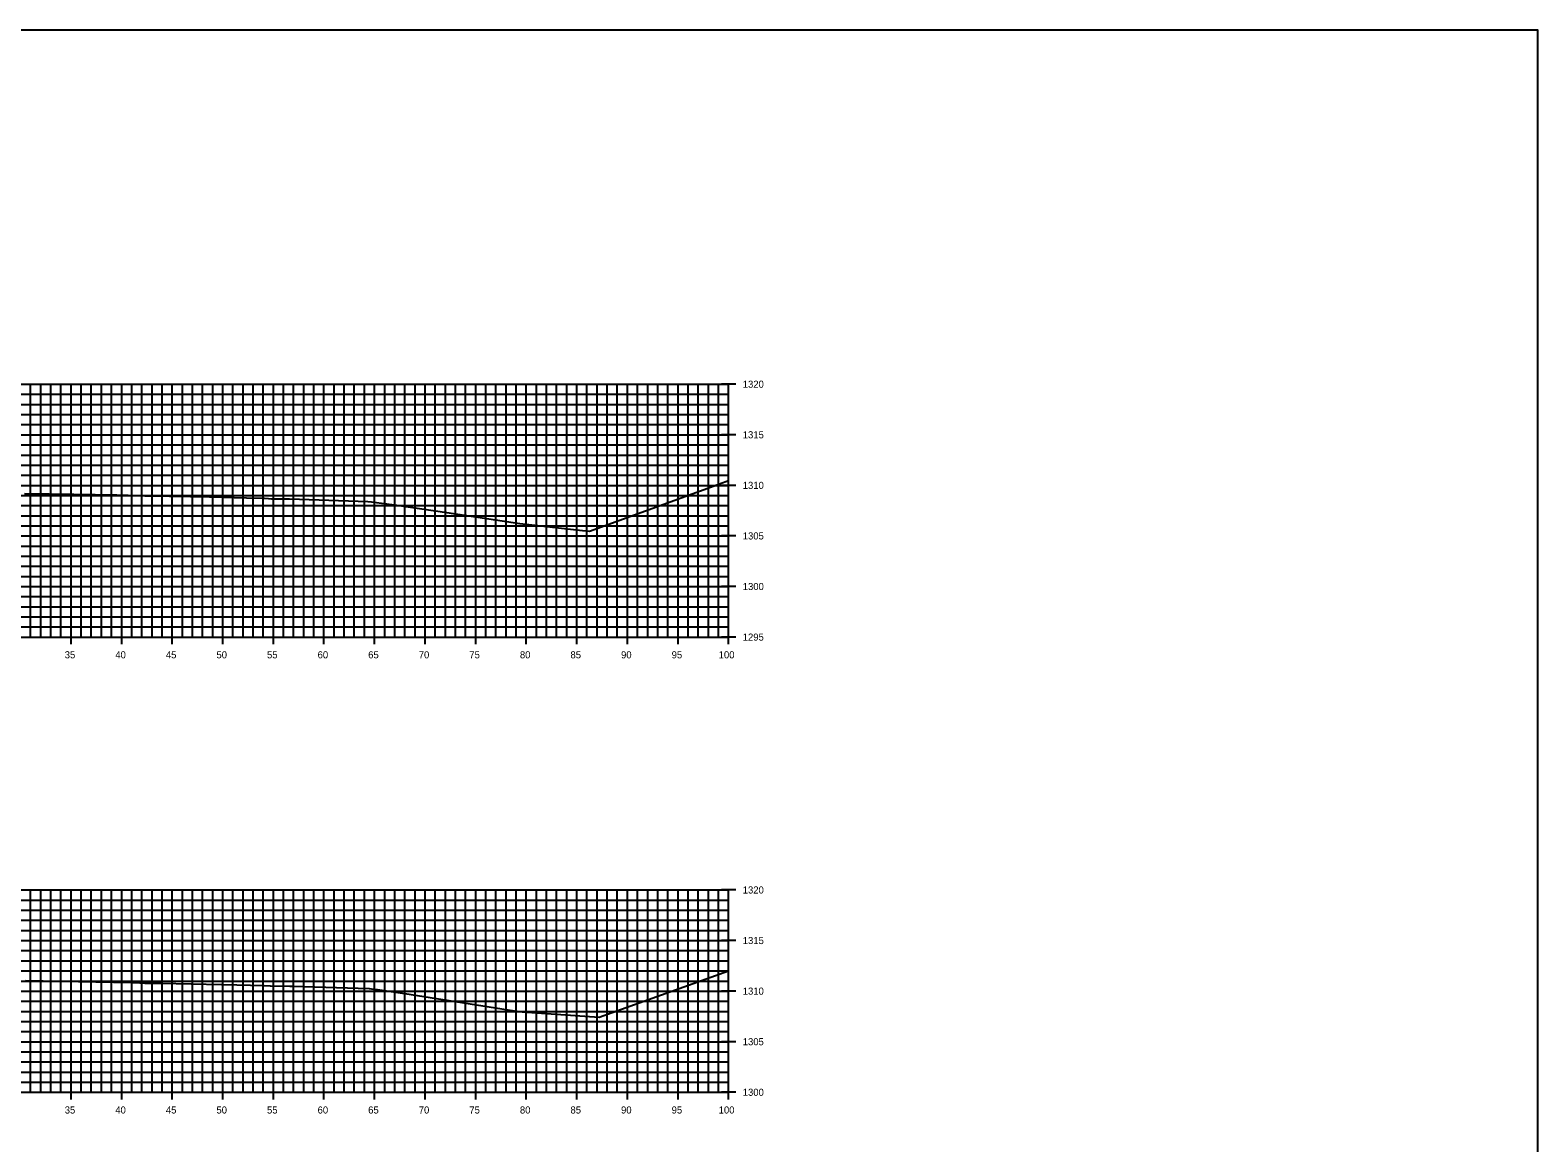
# Model space of a CAD drawing. Extents: x 674939 to 678919, y 750652 to 765176.
# Drawn here: x 678769.5 to 678918.5, y 753792.6 to 753902.6 of the extents above; entities that cross this region are included whole.
import ezdxf

# ---------------------------------------------------------------- set-up
doc = ezdxf.new("R2010")
doc.units = 0
for name, color, linetype in [('R_Axis', 7, 'Continuous'), ('R_Axis Annot', 7, 'Continuous'), ('R_Exist Surface', 7, 'Continuous'), ('R_Grid', 7, 'Continuous'), ('R_No Plot', 7, 'Continuous')]:
    doc.layers.add(name, color=color, linetype=linetype)

msp = doc.modelspace()

# ---------------------------------------------------------------- linework, layer by layer
at = {"layer": 'R_Axis'}
for p, q in [((678839.23, 753867.55), (678837.83, 753867.55)), ((678838.53, 753842.55), (678838.53, 753867.55)), ((678839.23, 753862.55), (678837.83, 753862.55)), ((678839.23, 753857.55), (678837.83, 753857.55)), ((678839.23, 753852.55), (678837.83, 753852.55)), ((678839.23, 753847.55), (678837.83, 753847.55)), ((678773.53, 753841.85), (678773.53, 753843.25)), ((678778.53, 753841.85), (678778.53, 753843.25)), ((678783.53, 753841.85), (678783.53, 753843.25)), ((678788.53, 753841.85), (678788.53, 753843.25)), ((678793.53, 753841.85), (678793.53, 753843.25)), ((678798.53, 753841.85), (678798.53, 753843.25)), ((678803.53, 753841.85), (678803.53, 753843.25)), ((678808.53, 753841.85), (678808.53, 753843.25)), ((678813.53, 753841.85), (678813.53, 753843.25)), ((678818.53, 753841.85), (678818.53, 753843.25)), ((678823.53, 753841.85), (678823.53, 753843.25)), ((678828.53, 753841.85), (678828.53, 753843.25)), ((678833.53, 753841.85), (678833.53, 753843.25)), ((678838.53, 753841.85), (678838.53, 753843.25)), ((678638.53, 753842.55), (678838.53, 753842.55)), ((678839.23, 753842.55), (678837.83, 753842.55)), ((678839.23, 753817.55), (678837.83, 753817.55)), ((678838.53, 753797.55), (678838.53, 753817.55)), ((678839.23, 753812.55), (678837.83, 753812.55)), ((678839.23, 753807.55), (678837.83, 753807.55)), ((678839.23, 753802.55), (678837.83, 753802.55)), ((678773.53, 753796.85), (678773.53, 753798.25)), ((678778.53, 753796.85), (678778.53, 753798.25)), ((678783.53, 753796.85), (678783.53, 753798.25)), ((678788.53, 753796.85), (678788.53, 753798.25)), ((678793.53, 753796.85), (678793.53, 753798.25)), ((678798.53, 753796.85), (678798.53, 753798.25)), ((678803.53, 753796.85), (678803.53, 753798.25)), ((678808.53, 753796.85), (678808.53, 753798.25)), ((678813.53, 753796.85), (678813.53, 753798.25)), ((678818.53, 753796.85), (678818.53, 753798.25)), ((678823.53, 753796.85), (678823.53, 753798.25)), ((678828.53, 753796.85), (678828.53, 753798.25)), ((678833.53, 753796.85), (678833.53, 753798.25)), ((678838.53, 753796.85), (678838.53, 753798.25)), ((678638.53, 753797.55), (678838.53, 753797.55)), ((678839.23, 753797.55), (678837.83, 753797.55))]:
    msp.add_line(p, q, dxfattribs=at)
at = {"layer": 'R_Exist Surface'}
for points in [[(678768.92, 753856.76), (678773.81, 753856.68), (678778.05, 753856.61), (678780.33, 753856.55), (678780.83, 753856.53), (678780.98, 753856.51), (678781.5, 753856.51), (678782.51, 753856.5), (678783.27, 753856.49), (678785.32, 753856.45), (678787.22, 753856.42), (678790.86, 753856.33), (678792.6, 753856.28), (678792.64, 753856.28), (678792.66, 753856.28), (678793.04, 753856.25), (678793.33, 753856.23), (678793.84, 753856.23), (678795.11, 753856.22), (678798.04, 753856.12), (678802.86, 753855.94), (678803.24, 753855.91), (678803.46, 753855.88), (678805.51, 753855.61), (678806.86, 753855.43), (678810.69, 753854.86), (678817.89, 753853.77), (678824.09, 753853.08), (678824.79, 753853.01), (678826.33, 753853.58), (678836.74, 753857.38), (678838.53, 753858.03)], [(678769.03, 753808.6), (678779.46, 753808.41), (678779.84, 753808.41), (678780.81, 753808.34), (678780.84, 753808.34), (678782.19, 753808.35), (678782.4, 753808.34), (678788.39, 753808.22), (678788.57, 753808.22), (678792.61, 753808.11), (678792.61, 753808.11), (678792.63, 753808.11), (678793.21, 753808.06), (678793.23, 753808.06), (678795.16, 753808.05), (678795.23, 753808.05), (678795.48, 753808.05), (678803.01, 753807.82), (678803.03, 753807.82), (678803.42, 753807.75), (678803.43, 753807.75), (678803.58, 753807.73), (678806.52, 753807.31), (678817.38, 753805.59), (678817.58, 753805.56), (678817.67, 753805.55), (678825.72, 753804.96), (678825.72, 753804.96), (678838.53, 753809.57)]]:
    msp.add_lwpolyline(points, dxfattribs=at)
at = {"layer": 'R_Grid'}
for p, q in [((678638.53, 753867.55), (678838.53, 753867.55)), ((678769.53, 753842.55), (678769.53, 753867.55)), ((678770.53, 753842.55), (678770.53, 753867.55)), ((678771.53, 753842.55), (678771.53, 753867.55)), ((678772.53, 753842.55), (678772.53, 753867.55)), ((678773.53, 753842.55), (678773.53, 753867.55)), ((678774.53, 753842.55), (678774.53, 753867.55)), ((678775.53, 753842.55), (678775.53, 753867.55)), ((678776.53, 753842.55), (678776.53, 753867.55)), ((678777.53, 753842.55), (678777.53, 753867.55)), ((678778.53, 753842.55), (678778.53, 753867.55)), ((678779.53, 753842.55), (678779.53, 753867.55)), ((678780.53, 753842.55), (678780.53, 753867.55)), ((678781.53, 753842.55), (678781.53, 753867.55)), ((678782.53, 753842.55), (678782.53, 753867.55)), ((678783.53, 753842.55), (678783.53, 753867.55)), ((678784.53, 753842.55), (678784.53, 753867.55)), ((678785.53, 753842.55), (678785.53, 753867.55)), ((678786.53, 753842.55), (678786.53, 753867.55)), ((678787.53, 753842.55), (678787.53, 753867.55)), ((678788.53, 753842.55), (678788.53, 753867.55)), ((678789.53, 753842.55), (678789.53, 753867.55)), ((678790.53, 753842.55), (678790.53, 753867.55)), ((678791.53, 753842.55), (678791.53, 753867.55)), ((678792.53, 753842.55), (678792.53, 753867.55)), ((678793.53, 753842.55), (678793.53, 753867.55)), ((678794.53, 753842.55), (678794.53, 753867.55)), ((678795.53, 753842.55), (678795.53, 753867.55)), ((678796.53, 753842.55), (678796.53, 753867.55)), ((678797.53, 753842.55), (678797.53, 753867.55)), ((678798.53, 753842.55), (678798.53, 753867.55)), ((678799.53, 753842.55), (678799.53, 753867.55)), ((678800.53, 753842.55), (678800.53, 753867.55)), ((678801.53, 753842.55), (678801.53, 753867.55)), ((678802.53, 753842.55), (678802.53, 753867.55)), ((678803.53, 753842.55), (678803.53, 753867.55)), ((678804.53, 753842.55), (678804.53, 753867.55)), ((678805.53, 753842.55), (678805.53, 753867.55)), ((678806.53, 753842.55), (678806.53, 753867.55)), ((678807.53, 753842.55), (678807.53, 753867.55)), ((678808.53, 753842.55), (678808.53, 753867.55)), ((678809.53, 753842.55), (678809.53, 753867.55)), ((678810.53, 753842.55), (678810.53, 753867.55)), ((678811.53, 753842.55), (678811.53, 753867.55)), ((678812.53, 753842.55), (678812.53, 753867.55)), ((678813.53, 753842.55), (678813.53, 753867.55)), ((678814.53, 753842.55), (678814.53, 753867.55)), ((678815.53, 753842.55), (678815.53, 753867.55)), ((678816.53, 753842.55), (678816.53, 753867.55)), ((678817.53, 753842.55), (678817.53, 753867.55)), ((678818.53, 753842.55), (678818.53, 753867.55)), ((678819.53, 753842.55), (678819.53, 753867.55)), ((678820.53, 753842.55), (678820.53, 753867.55)), ((678821.53, 753842.55), (678821.53, 753867.55)), ((678822.53, 753842.55), (678822.53, 753867.55)), ((678823.53, 753842.55), (678823.53, 753867.55)), ((678824.53, 753842.55), (678824.53, 753867.55)), ((678825.53, 753842.55), (678825.53, 753867.55)), ((678826.53, 753842.55), (678826.53, 753867.55)), ((678827.53, 753842.55), (678827.53, 753867.55)), ((678828.53, 753842.55), (678828.53, 753867.55)), ((678829.53, 753842.55), (678829.53, 753867.55)), ((678830.53, 753842.55), (678830.53, 753867.55)), ((678831.53, 753842.55), (678831.53, 753867.55)), ((678832.53, 753842.55), (678832.53, 753867.55)), ((678833.53, 753842.55), (678833.53, 753867.55)), ((678834.53, 753842.55), (678834.53, 753867.55)), ((678835.53, 753842.55), (678835.53, 753867.55)), ((678836.53, 753842.55), (678836.53, 753867.55)), ((678837.53, 753842.55), (678837.53, 753867.55)), ((678838.53, 753842.55), (678838.53, 753867.55)), ((678638.53, 753866.55), (678838.53, 753866.55)), ((678638.53, 753865.55), (678838.53, 753865.55)), ((678638.53, 753864.55), (678838.53, 753864.55)), ((678638.53, 753863.55), (678838.53, 753863.55)), ((678638.53, 753862.55), (678838.53, 753862.55)), ((678638.53, 753861.55), (678838.53, 753861.55)), ((678638.53, 753860.55), (678838.53, 753860.55)), ((678638.53, 753859.55), (678838.53, 753859.55)), ((678638.53, 753858.55), (678838.53, 753858.55)), ((678638.53, 753857.55), (678838.53, 753857.55)), ((678638.53, 753856.55), (678838.53, 753856.55)), ((678638.53, 753855.55), (678838.53, 753855.55)), ((678638.53, 753854.55), (678838.53, 753854.55)), ((678638.53, 753853.55), (678838.53, 753853.55)), ((678638.53, 753852.55), (678838.53, 753852.55)), ((678638.53, 753851.55), (678838.53, 753851.55)), ((678638.53, 753850.55), (678838.53, 753850.55)), ((678638.53, 753849.55), (678838.53, 753849.55)), ((678638.53, 753848.55), (678838.53, 753848.55)), ((678638.53, 753847.55), (678838.53, 753847.55)), ((678638.53, 753846.55), (678838.53, 753846.55)), ((678638.53, 753845.55), (678838.53, 753845.55)), ((678638.53, 753844.55), (678838.53, 753844.55)), ((678638.53, 753843.55), (678838.53, 753843.55)), ((678638.53, 753842.55), (678838.53, 753842.55)), ((678638.53, 753817.55), (678838.53, 753817.55)), ((678769.53, 753797.55), (678769.53, 753817.55)), ((678770.53, 753797.55), (678770.53, 753817.55)), ((678771.53, 753797.55), (678771.53, 753817.55)), ((678772.53, 753797.55), (678772.53, 753817.55)), ((678773.53, 753797.55), (678773.53, 753817.55)), ((678774.53, 753797.55), (678774.53, 753817.55)), ((678775.53, 753797.55), (678775.53, 753817.55)), ((678776.53, 753797.55), (678776.53, 753817.55)), ((678777.53, 753797.55), (678777.53, 753817.55)), ((678778.53, 753797.55), (678778.53, 753817.55)), ((678779.53, 753797.55), (678779.53, 753817.55)), ((678780.53, 753797.55), (678780.53, 753817.55)), ((678781.53, 753797.55), (678781.53, 753817.55)), ((678782.53, 753797.55), (678782.53, 753817.55)), ((678783.53, 753797.55), (678783.53, 753817.55)), ((678784.53, 753797.55), (678784.53, 753817.55)), ((678785.53, 753797.55), (678785.53, 753817.55)), ((678786.53, 753797.55), (678786.53, 753817.55)), ((678787.53, 753797.55), (678787.53, 753817.55)), ((678788.53, 753797.55), (678788.53, 753817.55)), ((678789.53, 753797.55), (678789.53, 753817.55)), ((678790.53, 753797.55), (678790.53, 753817.55)), ((678791.53, 753797.55), (678791.53, 753817.55)), ((678792.53, 753797.55), (678792.53, 753817.55)), ((678793.53, 753797.55), (678793.53, 753817.55)), ((678794.53, 753797.55), (678794.53, 753817.55)), ((678795.53, 753797.55), (678795.53, 753817.55)), ((678796.53, 753797.55), (678796.53, 753817.55)), ((678797.53, 753797.55), (678797.53, 753817.55)), ((678798.53, 753797.55), (678798.53, 753817.55)), ((678799.53, 753797.55), (678799.53, 753817.55)), ((678800.53, 753797.55), (678800.53, 753817.55)), ((678801.53, 753797.55), (678801.53, 753817.55)), ((678802.53, 753797.55), (678802.53, 753817.55)), ((678803.53, 753797.55), (678803.53, 753817.55)), ((678804.53, 753797.55), (678804.53, 753817.55)), ((678805.53, 753797.55), (678805.53, 753817.55)), ((678806.53, 753797.55), (678806.53, 753817.55)), ((678807.53, 753797.55), (678807.53, 753817.55)), ((678808.53, 753797.55), (678808.53, 753817.55)), ((678809.53, 753797.55), (678809.53, 753817.55)), ((678810.53, 753797.55), (678810.53, 753817.55)), ((678811.53, 753797.55), (678811.53, 753817.55)), ((678812.53, 753797.55), (678812.53, 753817.55)), ((678813.53, 753797.55), (678813.53, 753817.55)), ((678814.53, 753797.55), (678814.53, 753817.55)), ((678815.53, 753797.55), (678815.53, 753817.55)), ((678816.53, 753797.55), (678816.53, 753817.55)), ((678817.53, 753797.55), (678817.53, 753817.55)), ((678818.53, 753797.55), (678818.53, 753817.55)), ((678819.53, 753797.55), (678819.53, 753817.55)), ((678820.53, 753797.55), (678820.53, 753817.55)), ((678821.53, 753797.55), (678821.53, 753817.55)), ((678822.53, 753797.55), (678822.53, 753817.55)), ((678823.53, 753797.55), (678823.53, 753817.55)), ((678824.53, 753797.55), (678824.53, 753817.55)), ((678825.53, 753797.55), (678825.53, 753817.55)), ((678826.53, 753797.55), (678826.53, 753817.55)), ((678827.53, 753797.55), (678827.53, 753817.55)), ((678828.53, 753797.55), (678828.53, 753817.55)), ((678829.53, 753797.55), (678829.53, 753817.55)), ((678830.53, 753797.55), (678830.53, 753817.55)), ((678831.53, 753797.55), (678831.53, 753817.55)), ((678832.53, 753797.55), (678832.53, 753817.55)), ((678833.53, 753797.55), (678833.53, 753817.55)), ((678834.53, 753797.55), (678834.53, 753817.55)), ((678835.53, 753797.55), (678835.53, 753817.55)), ((678836.53, 753797.55), (678836.53, 753817.55)), ((678837.53, 753797.55), (678837.53, 753817.55)), ((678838.53, 753797.55), (678838.53, 753817.55)), ((678638.53, 753816.55), (678838.53, 753816.55)), ((678638.53, 753815.55), (678838.53, 753815.55)), ((678638.53, 753814.55), (678838.53, 753814.55)), ((678638.53, 753813.55), (678838.53, 753813.55)), ((678638.53, 753812.55), (678838.53, 753812.55)), ((678638.53, 753811.55), (678838.53, 753811.55)), ((678638.53, 753810.55), (678838.53, 753810.55)), ((678638.53, 753809.55), (678838.53, 753809.55)), ((678638.53, 753808.55), (678838.53, 753808.55)), ((678638.53, 753807.55), (678838.53, 753807.55)), ((678638.53, 753806.55), (678838.53, 753806.55)), ((678638.53, 753805.55), (678838.53, 753805.55)), ((678638.53, 753804.55), (678838.53, 753804.55)), ((678638.53, 753803.55), (678838.53, 753803.55)), ((678638.53, 753802.55), (678838.53, 753802.55)), ((678638.53, 753801.55), (678838.53, 753801.55)), ((678638.53, 753800.55), (678838.53, 753800.55)), ((678638.53, 753799.55), (678838.53, 753799.55)), ((678638.53, 753798.55), (678838.53, 753798.55)), ((678638.53, 753797.55), (678838.53, 753797.55))]:
    msp.add_line(p, q, dxfattribs=at)
at = {"layer": 'R_No Plot'}
msp.add_lwpolyline([(678578.53, 753682.55), (678918.53, 753682.55), (678918.53, 753902.55), (678578.53, 753902.55)], close=True, dxfattribs=at)

# ---------------------------------------------------------------- texts
at = {"layer": 'R_Axis Annot'}
for s, p in [('1320', (678839.93, 753867.2)), ('1315', (678839.93, 753862.2)), ('1310', (678839.93, 753857.2)), ('1305', (678839.93, 753852.2)), ('1300', (678839.93, 753847.2)), ('1295', (678839.93, 753842.2)), ('35', (678772.9, 753840.45)), ('40', (678777.9, 753840.45)), ('45', (678782.9, 753840.45)), ('50', (678787.9, 753840.45)), ('55', (678792.9, 753840.45)), ('60', (678797.9, 753840.45)), ('65', (678802.9, 753840.45)), ('70', (678807.9, 753840.45)), ('75', (678812.9, 753840.45)), ('80', (678817.9, 753840.45)), ('85', (678822.9, 753840.45)), ('90', (678827.9, 753840.45)), ('95', (678832.9, 753840.45)), ('100', (678837.55, 753840.45)), ('1320', (678839.93, 753817.2)), ('1315', (678839.93, 753812.2)), ('1310', (678839.93, 753807.2)), ('1305', (678839.93, 753802.2)), ('1300', (678839.93, 753797.2)), ('35', (678772.9, 753795.45)), ('40', (678777.9, 753795.45)), ('45', (678782.9, 753795.45)), ('50', (678787.9, 753795.45)), ('55', (678792.9, 753795.45)), ('60', (678797.9, 753795.45)), ('65', (678802.9, 753795.45)), ('70', (678807.9, 753795.45)), ('75', (678812.9, 753795.45)), ('80', (678817.9, 753795.45)), ('85', (678822.9, 753795.45)), ('90', (678827.9, 753795.45)), ('95', (678832.9, 753795.45)), ('100', (678837.55, 753795.45))]:
    msp.add_text(s, height=0.7, dxfattribs=at).set_placement(p)

doc.saveas('drawing.dxf')
